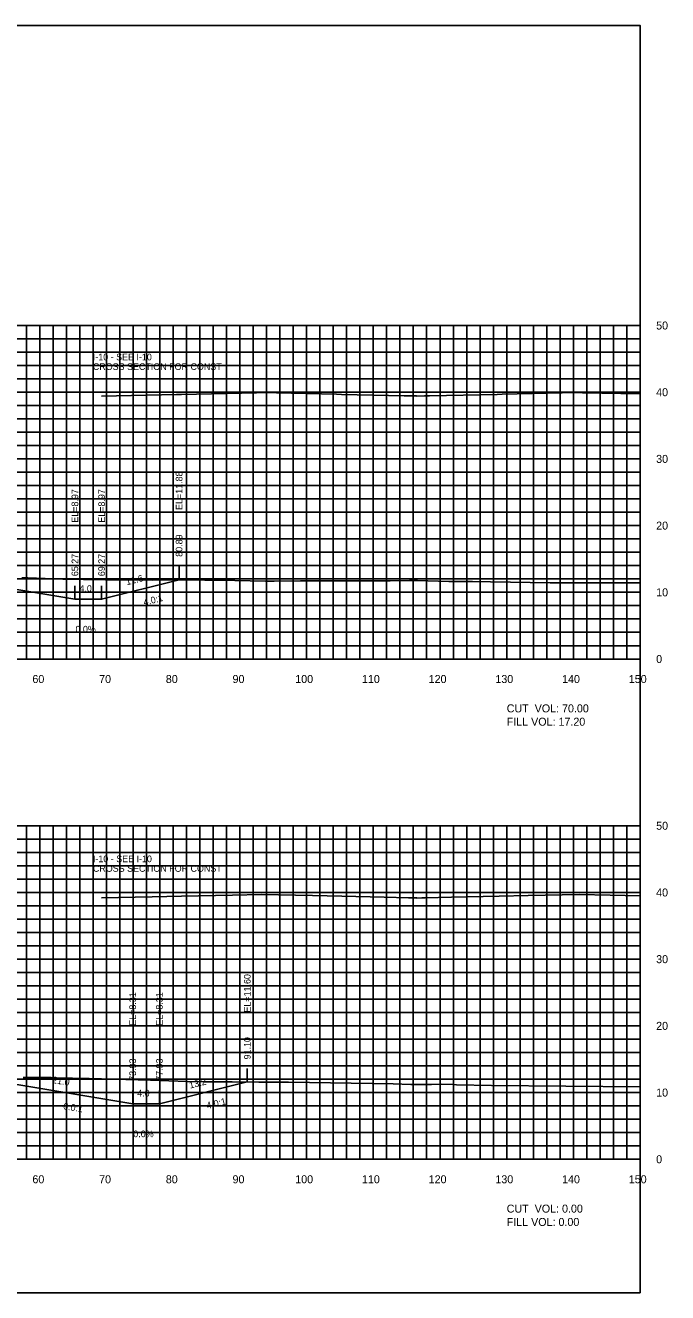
# Model space of a CAD drawing. Extents: x 1797714 to 1804825, y 249015 to 250269.
# Drawn here: x 1802348.8 to 1802445.1, y 250079.4 to 250269.4 of the extents above; entities that cross this region are included whole.
import ezdxf

# ---------------------------------------------------------------- set-up
doc = ezdxf.new("R2010")
doc.units = 0
for name, color, linetype in [('10', 7, 'Continuous'), ('3', 7, 'Continuous'), ('31', 7, 'Continuous'), ('4', 7, 'Continuous'), ('60', 7, 'Continuous'), ('ANNO-TXT', 7, 'Continuous'), ('CL-CNST', 7, 'Continuous'), ('Level 62', 7, 'Continuous'), ('M-ROADS', 7, 'Continuous')]:
    doc.layers.add(name, color=color, linetype=linetype)

msp = doc.modelspace()

# ---------------------------------------------------------------- linework, layer by layer
for p, q in [((1802371.89, 250186.31), (1802371.89, 250188.31)), ((1802356.27, 250183.4), (1802356.27, 250185.4)), ((1802360.27, 250183.4), (1802360.27, 250185.4)), ((1802382.11, 250111.03), (1802382.11, 250113.03)), ((1802364.93, 250107.74), (1802364.93, 250109.74)), ((1802368.93, 250107.74), (1802368.93, 250109.74))]:
    msp.add_line(p, q)
msp.add_lwpolyline([(1802141, 250079.43), (1802441, 250079.43), (1802441, 250269.43), (1802141, 250269.43)], close=True)
at = {"layer": '60'}
for p, q in [((1802441, 250174.43), (1802441, 250224.43)), ((1802441.06, 250224.43), (1802441, 250224.43)), ((1802441.06, 250214.43), (1802441, 250214.43)), ((1802441.06, 250204.43), (1802441, 250204.43)), ((1802441.06, 250194.43), (1802441, 250194.43)), ((1802441.06, 250184.43), (1802441, 250184.43)), ((1802141, 250174.43), (1802441, 250174.43)), ((1802351, 250174.37), (1802351, 250174.43)), ((1802361, 250174.37), (1802361, 250174.43)), ((1802371, 250174.37), (1802371, 250174.43)), ((1802381, 250174.37), (1802381, 250174.43)), ((1802391, 250174.37), (1802391, 250174.43)), ((1802401, 250174.37), (1802401, 250174.43)), ((1802411, 250174.37), (1802411, 250174.43)), ((1802421, 250174.37), (1802421, 250174.43)), ((1802431, 250174.37), (1802431, 250174.43)), ((1802441, 250174.37), (1802441, 250174.43)), ((1802441.06, 250174.43), (1802441, 250174.43)), ((1802441, 250099.43), (1802441, 250149.43)), ((1802441.06, 250149.43), (1802441, 250149.43)), ((1802441.06, 250139.43), (1802441, 250139.43)), ((1802441.06, 250129.43), (1802441, 250129.43)), ((1802441.06, 250119.43), (1802441, 250119.43)), ((1802441.06, 250109.43), (1802441, 250109.43)), ((1802141, 250099.43), (1802441, 250099.43)), ((1802351, 250099.37), (1802351, 250099.43)), ((1802361, 250099.37), (1802361, 250099.43)), ((1802371, 250099.37), (1802371, 250099.43)), ((1802381, 250099.37), (1802381, 250099.43)), ((1802391, 250099.37), (1802391, 250099.43)), ((1802401, 250099.37), (1802401, 250099.43)), ((1802411, 250099.37), (1802411, 250099.43)), ((1802421, 250099.37), (1802421, 250099.43)), ((1802431, 250099.37), (1802431, 250099.43)), ((1802441, 250099.37), (1802441, 250099.43)), ((1802441.06, 250099.43), (1802441, 250099.43))]:
    msp.add_line(p, q, dxfattribs=at)
at = {"layer": 'CL-CNST'}
for points in [[(1802360.25, 250213.85), (1802371.5, 250214.1), (1802372.25, 250214.11), (1802383.5, 250214.36), (1802384.25, 250214.38), (1802395.5, 250214.13), (1802396.25, 250214.11), (1802405.63, 250213.91), (1802406.25, 250213.89), (1802407.42, 250213.87), (1802407.5, 250213.87), (1802407.5, 250213.85), (1802407.5, 250213.85), (1802408.67, 250213.87), (1802408.75, 250213.87), (1802409.41, 250213.89), (1802419.57, 250214.11), (1802420.31, 250214.13), (1802431.57, 250214.38), (1802432.34, 250214.36), (1802441, 250214.17)], [(1802253.02, 250187.53), (1802255.92, 250188.49), (1802256.92, 250188.45), (1802266.92, 250188.3), (1802272.75, 250188.07), (1802273.08, 250188.07), (1802273.25, 250187.57), (1802275.25, 250187.73), (1802291, 250188.08), (1802324.2, 250187.35), (1802328.2, 250187.19), (1802335.27, 250186.9), (1802356.27, 250183.4), (1802360.27, 250183.4), (1802371.89, 250186.31)], [(1802360.26, 250138.61), (1802367.87, 250138.78), (1802372.26, 250138.87), (1802379.88, 250139.04), (1802384.26, 250139.14), (1802391.88, 250138.97), (1802396.26, 250138.87), (1802402.61, 250138.73), (1802406.26, 250138.65), (1802407.05, 250138.63), (1802407.51, 250138.62), (1802407.51, 250138.61), (1802407.51, 250138.6), (1802408.3, 250138.62), (1802408.76, 250138.63), (1802412.72, 250138.71), (1802419.85, 250138.87), (1802424.23, 250138.97), (1802431.85, 250139.14), (1802436.53, 250139.03), (1802441, 250138.93)], [(1802242.63, 250111.99), (1802244.47, 250112.6), (1802245.47, 250112.56), (1802255.47, 250112.41), (1802260.12, 250112.23), (1802260.45, 250112.23), (1802260.62, 250111.73), (1802262.62, 250111.89), (1802291, 250112.51), (1802337.93, 250111.48), (1802341.93, 250111.32), (1802343.93, 250111.24), (1802364.93, 250107.74), (1802368.93, 250107.74), (1802382.11, 250111.03)]]:
    msp.add_lwpolyline(points, dxfattribs=at)
at = {"layer": 'Level 62'}
for p, q in [((1802141, 250224.43), (1802441, 250224.43)), ((1802349, 250174.43), (1802349, 250224.43)), ((1802351, 250174.43), (1802351, 250224.43)), ((1802353, 250174.43), (1802353, 250224.43)), ((1802355, 250174.43), (1802355, 250224.43)), ((1802357, 250174.43), (1802357, 250224.43)), ((1802359, 250174.43), (1802359, 250224.43)), ((1802361, 250174.43), (1802361, 250224.43)), ((1802363, 250174.43), (1802363, 250224.43)), ((1802365, 250174.43), (1802365, 250224.43)), ((1802367, 250174.43), (1802367, 250224.43)), ((1802369, 250174.43), (1802369, 250224.43)), ((1802371, 250174.43), (1802371, 250224.43)), ((1802373, 250174.43), (1802373, 250224.43)), ((1802375, 250174.43), (1802375, 250224.43)), ((1802377, 250174.43), (1802377, 250224.43)), ((1802379, 250174.43), (1802379, 250224.43)), ((1802381, 250174.43), (1802381, 250224.43)), ((1802383, 250174.43), (1802383, 250224.43)), ((1802385, 250174.43), (1802385, 250224.43)), ((1802387, 250174.43), (1802387, 250224.43)), ((1802389, 250174.43), (1802389, 250224.43)), ((1802391, 250174.43), (1802391, 250224.43)), ((1802393, 250174.43), (1802393, 250224.43)), ((1802395, 250174.43), (1802395, 250224.43)), ((1802397, 250174.43), (1802397, 250224.43)), ((1802399, 250174.43), (1802399, 250224.43)), ((1802401, 250174.43), (1802401, 250224.43)), ((1802403, 250174.43), (1802403, 250224.43)), ((1802405, 250174.43), (1802405, 250224.43)), ((1802407, 250174.43), (1802407, 250224.43)), ((1802409, 250174.43), (1802409, 250224.43)), ((1802411, 250174.43), (1802411, 250224.43)), ((1802413, 250174.43), (1802413, 250224.43)), ((1802415, 250174.43), (1802415, 250224.43)), ((1802417, 250174.43), (1802417, 250224.43)), ((1802419, 250174.43), (1802419, 250224.43)), ((1802421, 250174.43), (1802421, 250224.43)), ((1802423, 250174.43), (1802423, 250224.43)), ((1802425, 250174.43), (1802425, 250224.43)), ((1802427, 250174.43), (1802427, 250224.43)), ((1802429, 250174.43), (1802429, 250224.43)), ((1802431, 250174.43), (1802431, 250224.43)), ((1802433, 250174.43), (1802433, 250224.43)), ((1802435, 250174.43), (1802435, 250224.43)), ((1802437, 250174.43), (1802437, 250224.43)), ((1802439, 250174.43), (1802439, 250224.43)), ((1802441, 250174.43), (1802441, 250224.43)), ((1802141, 250222.43), (1802441, 250222.43)), ((1802141, 250220.43), (1802441, 250220.43)), ((1802141, 250218.43), (1802441, 250218.43)), ((1802141, 250216.43), (1802441, 250216.43)), ((1802141, 250214.43), (1802441, 250214.43)), ((1802141, 250212.43), (1802441, 250212.43)), ((1802141, 250210.43), (1802441, 250210.43)), ((1802141, 250208.43), (1802441, 250208.43)), ((1802141, 250206.43), (1802441, 250206.43)), ((1802141, 250204.43), (1802441, 250204.43)), ((1802141, 250202.43), (1802441, 250202.43)), ((1802141, 250200.43), (1802441, 250200.43)), ((1802141, 250198.43), (1802441, 250198.43)), ((1802141, 250196.43), (1802441, 250196.43)), ((1802141, 250194.43), (1802441, 250194.43)), ((1802141, 250192.43), (1802441, 250192.43)), ((1802141, 250190.43), (1802441, 250190.43)), ((1802141, 250188.43), (1802441, 250188.43)), ((1802141, 250186.43), (1802441, 250186.43)), ((1802141, 250184.43), (1802441, 250184.43)), ((1802141, 250182.43), (1802441, 250182.43)), ((1802141, 250180.43), (1802441, 250180.43)), ((1802141, 250178.43), (1802441, 250178.43)), ((1802141, 250176.43), (1802441, 250176.43)), ((1802141, 250174.43), (1802441, 250174.43)), ((1802141, 250149.43), (1802441, 250149.43)), ((1802349, 250099.43), (1802349, 250149.43)), ((1802351, 250099.43), (1802351, 250149.43)), ((1802353, 250099.43), (1802353, 250149.43)), ((1802355, 250099.43), (1802355, 250149.43)), ((1802357, 250099.43), (1802357, 250149.43)), ((1802359, 250099.43), (1802359, 250149.43)), ((1802361, 250099.43), (1802361, 250149.43)), ((1802363, 250099.43), (1802363, 250149.43)), ((1802365, 250099.43), (1802365, 250149.43)), ((1802367, 250099.43), (1802367, 250149.43)), ((1802369, 250099.43), (1802369, 250149.43)), ((1802371, 250099.43), (1802371, 250149.43)), ((1802373, 250099.43), (1802373, 250149.43)), ((1802375, 250099.43), (1802375, 250149.43)), ((1802377, 250099.43), (1802377, 250149.43)), ((1802379, 250099.43), (1802379, 250149.43)), ((1802381, 250099.43), (1802381, 250149.43)), ((1802383, 250099.43), (1802383, 250149.43)), ((1802385, 250099.43), (1802385, 250149.43)), ((1802387, 250099.43), (1802387, 250149.43)), ((1802389, 250099.43), (1802389, 250149.43)), ((1802391, 250099.43), (1802391, 250149.43)), ((1802393, 250099.43), (1802393, 250149.43)), ((1802395, 250099.43), (1802395, 250149.43)), ((1802397, 250099.43), (1802397, 250149.43)), ((1802399, 250099.43), (1802399, 250149.43)), ((1802401, 250099.43), (1802401, 250149.43)), ((1802403, 250099.43), (1802403, 250149.43)), ((1802405, 250099.43), (1802405, 250149.43)), ((1802407, 250099.43), (1802407, 250149.43)), ((1802409, 250099.43), (1802409, 250149.43)), ((1802411, 250099.43), (1802411, 250149.43)), ((1802413, 250099.43), (1802413, 250149.43)), ((1802415, 250099.43), (1802415, 250149.43)), ((1802417, 250099.43), (1802417, 250149.43)), ((1802419, 250099.43), (1802419, 250149.43)), ((1802421, 250099.43), (1802421, 250149.43)), ((1802423, 250099.43), (1802423, 250149.43)), ((1802425, 250099.43), (1802425, 250149.43)), ((1802427, 250099.43), (1802427, 250149.43)), ((1802429, 250099.43), (1802429, 250149.43)), ((1802431, 250099.43), (1802431, 250149.43)), ((1802433, 250099.43), (1802433, 250149.43)), ((1802435, 250099.43), (1802435, 250149.43)), ((1802437, 250099.43), (1802437, 250149.43)), ((1802439, 250099.43), (1802439, 250149.43)), ((1802441, 250099.43), (1802441, 250149.43)), ((1802141, 250147.43), (1802441, 250147.43)), ((1802141, 250145.43), (1802441, 250145.43)), ((1802141, 250143.43), (1802441, 250143.43)), ((1802141, 250141.43), (1802441, 250141.43)), ((1802141, 250139.43), (1802441, 250139.43)), ((1802141, 250137.43), (1802441, 250137.43)), ((1802141, 250135.43), (1802441, 250135.43)), ((1802141, 250133.43), (1802441, 250133.43)), ((1802141, 250131.43), (1802441, 250131.43)), ((1802141, 250129.43), (1802441, 250129.43)), ((1802141, 250127.43), (1802441, 250127.43)), ((1802141, 250125.43), (1802441, 250125.43)), ((1802141, 250123.43), (1802441, 250123.43)), ((1802141, 250121.43), (1802441, 250121.43)), ((1802141, 250119.43), (1802441, 250119.43)), ((1802141, 250117.43), (1802441, 250117.43)), ((1802141, 250115.43), (1802441, 250115.43)), ((1802141, 250113.43), (1802441, 250113.43)), ((1802141, 250111.43), (1802441, 250111.43)), ((1802141, 250109.43), (1802441, 250109.43)), ((1802141, 250107.43), (1802441, 250107.43)), ((1802141, 250105.43), (1802441, 250105.43)), ((1802141, 250103.43), (1802441, 250103.43)), ((1802141, 250101.43), (1802441, 250101.43)), ((1802141, 250099.43), (1802441, 250099.43))]:
    msp.add_line(p, q, dxfattribs=at)
at = {"layer": 'M-ROADS'}
for points in [[(1802348.32, 250186.61), (1802349.22, 250186.62), (1802354.48, 250186.41), (1802357.57, 250186.36), (1802360.85, 250186.3), (1802367.83, 250186.26), (1802369.02, 250186.28), (1802371.21, 250186.32), (1802380.25, 250186.22), (1802384.82, 250186.11), (1802385.13, 250186.1), (1802385.94, 250186.1), (1802386.13, 250186.1), (1802390.09, 250186.15), (1802397.54, 250186.16), (1802403.52, 250186.17), (1802406.41, 250186.21), (1802406.7, 250186.21), (1802406.76, 250186.21), (1802406.97, 250186.21), (1802407.62, 250186.18), (1802412.32, 250186.05), (1802413.47, 250186.05), (1802413.71, 250186.05), (1802414.54, 250186.05), (1802415.87, 250186.03), (1802418.59, 250185.98), (1802427.52, 250185.84), (1802441, 250185.85)], [(1802348.53, 250111.71), (1802350.02, 250111.71), (1802350.34, 250111.71), (1802351.42, 250111.71), (1802352.71, 250111.71), (1802353.45, 250111.62), (1802358.42, 250111.56), (1802367.62, 250111.29), (1802373.08, 250111.07), (1802375.67, 250111.05), (1802376.39, 250111.05), (1802376.6, 250111.05), (1802377.6, 250111.05), (1802379.82, 250111.05), (1802383.83, 250111.01), (1802388.31, 250110.99), (1802403.99, 250110.76), (1802406.64, 250110.66), (1802409.7, 250110.63), (1802411.21, 250110.67), (1802413, 250110.62), (1802413.45, 250110.57), (1802418.72, 250110.47), (1802441, 250110.28)]]:
    msp.add_lwpolyline(points, dxfattribs=at)

# ---------------------------------------------------------------- texts
for s, rotation, p in [('4.0:1', 14.0362, (1802366.68, 250182.43)), ('4.0:1', 14.0362, (1802376.13, 250106.96)), ('-6.0:1', 350.5377, (1802354.02, 250107.02))]:
    msp.add_text(s, height=1, rotation=rotation).set_placement(p)
at = {"layer": '10'}
for s, p in [('60', (1802349.9, 250170.83)), ('70', (1802359.9, 250170.83)), ('80', (1802369.9, 250170.83)), ('90', (1802379.9, 250170.83)), ('100', (1802389.3, 250170.83)), ('110', (1802399.3, 250170.83)), ('120', (1802409.3, 250170.83)), ('130', (1802419.3, 250170.83)), ('140', (1802429.3, 250170.83)), ('150', (1802439.3, 250170.83)), ('60', (1802349.9, 250095.83)), ('70', (1802359.9, 250095.83)), ('80', (1802369.9, 250095.83)), ('90', (1802379.9, 250095.83)), ('100', (1802389.3, 250095.83)), ('110', (1802399.3, 250095.83)), ('120', (1802409.3, 250095.83)), ('130', (1802419.3, 250095.83)), ('140', (1802429.3, 250095.83)), ('150', (1802439.3, 250095.83))]:
    msp.add_text(s, height=1.2, dxfattribs=at).set_placement(p)
at = {"layer": '3'}
for s, p in [('CROSS SECTION FOR CONST ', (1802358.96, 250217.77)), ('I-10 - SEE I-10 ', (1802358.96, 250219.21)), ('I-10 - SEE I-10 ', (1802358.97, 250143.97)), ('CROSS SECTION FOR CONST ', (1802358.97, 250142.53))]:
    msp.add_text(s, height=1, dxfattribs=at).set_placement(p)
for s, p in [('EL=11.88', (1802372.39, 250196.78)), ('EL=8.97', (1802356.77, 250194.87)), ('EL=8.97', (1802360.77, 250194.87)), ('80.89', (1802372.39, 250189.76)), ('65.27', (1802356.77, 250186.85)), ('69.27', (1802360.77, 250186.85)), ('EL=11.60', (1802382.61, 250121.43)), ('EL=8.31', (1802365.43, 250119.45)), ('EL=8.31', (1802369.43, 250119.45)), ('91.10', (1802382.61, 250114.4)), ('73.93', (1802365.43, 250111.19)), ('77.93', (1802369.43, 250111.19))]:
    msp.add_text(s, height=1, rotation=90, dxfattribs=at).set_placement(p)
at = {"layer": '31'}
for s, p in [('50', (1802443.4, 250223.83)), ('40', (1802443.4, 250213.83)), ('30', (1802443.4, 250203.83)), ('20', (1802443.4, 250193.83)), ('10', (1802443.4, 250183.83)), ('0', (1802443.4, 250173.83)), ('50', (1802443.4, 250148.83)), ('40', (1802443.4, 250138.83)), ('30', (1802443.4, 250128.83)), ('20', (1802443.4, 250118.83)), ('10', (1802443.4, 250108.83)), ('0', (1802443.4, 250098.83))]:
    msp.add_text(s, height=1.2, dxfattribs=at).set_placement(p)
at = {"layer": '4'}
for s, rotation, p in [('11.6', 14.0362, (1802364.06, 250185.49)), ('21.0', 350.5377, (1802352.82, 250110.87)), ('13.2', 14.0362, (1802373.53, 250110.02))]:
    msp.add_text(s, height=1, rotation=rotation, dxfattribs=at).set_placement(p)
for s, p in [('4.0', (1802356.95, 250184.5)), ('0.0%', (1802356.36, 250178.4)), ('4.0', (1802365.61, 250108.84)), ('0.0%', (1802365.02, 250102.74))]:
    msp.add_text(s, height=1, dxfattribs=at).set_placement(p)
at = {"layer": 'ANNO-TXT'}
for s, p in [('CUT  VOL: 70.00', (1802421, 250166.43)), ('FILL VOL: 17.20', (1802421, 250164.43)), ('CUT  VOL: 0.00', (1802421, 250091.43)), ('FILL VOL: 0.00', (1802421, 250089.43))]:
    msp.add_text(s, height=1.2, dxfattribs=at).set_placement(p)

doc.saveas('drawing.dxf')
